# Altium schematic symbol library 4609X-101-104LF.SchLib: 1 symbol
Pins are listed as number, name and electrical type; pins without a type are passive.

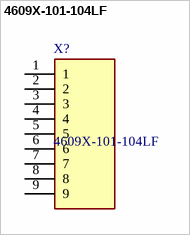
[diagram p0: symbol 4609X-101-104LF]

## 4609X-101-104LF
designator X?
Resistor Networks & Arrays 9pins 100Kohms Bussed; Manufacturer_Name: Bourns; Geometry.Height: 5.08mm
footprint 4609X101104LF
pins: 1, 2, 3, 4, 5, 6, 7, 8, 9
